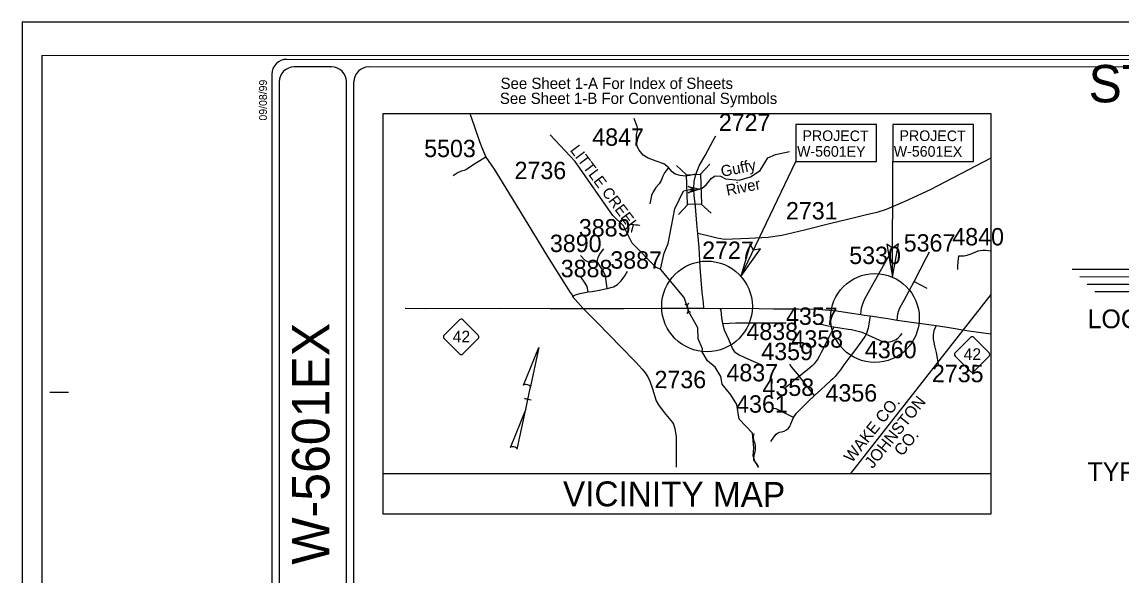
# Model space of a CAD drawing. Extents: x 2105791 to 2114488, y 667759 to 673441.
# Drawn here: x 2105791 to 2109589, y 671528 to 673441 of the extents above; entities that cross this region are included whole.
import ezdxf

# ---------------------------------------------------------------- set-up
doc = ezdxf.new("R2010")
doc.units = 0
for name, color, linetype in [('Default', 7, 'Continuous'), ('Exist Boundary Political CountyLine', 7, 'Continuous'), ('Exist Road Primary NC Attributed', 7, 'Continuous'), ('Exist Road Secondary Type 51 Attributed', 7, 'Continuous'), ('Old_Level_1', 7, 'Continuous'), ('Old_Level_8', 7, 'Continuous'), ('Prop North Arrow for Plan Sheets CELL', 7, 'Continuous'), ('Prop PHM Highway Shield CELL', 7, 'Continuous'), ('Sheet Cutting Line CELL', 7, 'Continuous'), ('Sheet Plot Border Inside CELL', 7, 'Continuous'), ('Sheet Plot Border Outside CELL', 7, 'Continuous'), ('Sheet Title CELL', 7, 'Continuous')]:
    doc.layers.add(name, color=color, linetype=linetype)

msp = doc.modelspace()

# ---------------------------------------------------------------- linework, layer by layer
at = {"layer": 'Default'}
for p, q in [((2108053.4, 672945.8), (2108087.6, 672913.7)), ((2108167.8, 672949.5), (2108135.6, 672915.2)), ((2108091.7, 672810.9), (2108059.6, 672776.7)), ((2108138.7, 672812.4), (2108172.9, 672780.3)), ((2108081.8, 672466.4), (2108089.4, 672462.3)), ((2108094, 672469.6), (2108089.4, 672462.3)), ((2108089.4, 672462.3), (2108094.6, 672442.3)), ((2108090, 672435), (2108094.6, 672442.3)), ((2108102.1, 672438.2), (2108094.6, 672442.3))]:
    msp.add_line(p, q, dxfattribs=at)
for points in [[(2107997.2, 672587.5), (2107982.4, 672593.3), (2107900.2, 672677.4), (2107869.3, 672737.3), (2107833.3, 672772.7), (2107702.9, 672959.2), (2107616.4, 673051.2)], [(2108077.1, 672857.7), (2108098.9, 672862.3), (2108103.9, 672862.9), (2108112.7, 672862.5), (2108117.5, 672861.9), (2108141.4, 672867.2), (2108155.4, 672878.9), (2108173.4, 672902.2), (2108186.5, 672910), (2108205.3, 672909), (2108222.1, 672899.3), (2108269, 672895.2), (2108308.9, 672905.9), (2108342.4, 672927.8), (2108369, 672971.5), (2108394.6, 672983.2), (2108443.8, 672993.2)], [(2108112.7, 672862.5), (2108112.7, 672867.6), (2108114.5, 672890.3), (2108119.7, 672914.3)], [(2107997.2, 672587.5), (2108010.2, 672642.9), (2108024.4, 672675.7), (2108046.7, 672796), (2108077.1, 672857.7)], [(2108335.9, 671904.3), (2108323.1, 671925.2), (2108318.3, 671943.5), (2108319.6, 671970.7), (2108315.7, 672020.9), (2108269.3, 672069.6), (2108261.3, 672120.8), (2108240.6, 672153.8), (2108210.7, 672190.6), (2108206, 672216.4), (2108186.8, 672248.9), (2108159.5, 672270.8), (2108141.4, 672302), (2108142.2, 672312.1), (2108127.7, 672347.1), (2108127, 672385.1), (2108100, 672432.7), (2108094.8, 672437.7), (2108093.5, 672440.8), (2108093.3, 672447.1), (2108092, 672452.3), (2108090.3, 672458.2), (2108079.6, 672490.2), (2107997.2, 672587.5)], [(2108320, 672020), (2108318.8, 672015.8), (2108317.9, 672010), (2108317.5, 672006.6), (2108318.7, 671998.7), (2108320.2, 671994.6), (2108322.1, 671989), (2108324, 671984.4), (2108325.3, 671979.3), (2108325, 671971.3), (2108324.2, 671964.2), (2108323.2, 671957.5), (2108322, 671951.9), (2108320.1, 671944.5), (2108318.6, 671934.4), (2108318.5, 671933.8), (2108319.5, 671928.3), (2108321.9, 671925.1), (2108325.7, 671920.1), (2108329.6, 671915.4), (2108332.4, 671910.4), (2108335.8, 671904.3)]]:
    msp.add_lwpolyline(points, dxfattribs=at)
for points in [[(2108135.6, 672915.2), (2108138.9, 672812.4), (2108090.9, 672810.9), (2108087.6, 672913.7)], [(2108093, 672872.5), (2108133.5, 672863.3), (2108093.8, 672851), (2108112.7, 672862.5)]]:
    msp.add_lwpolyline(points, close=True, dxfattribs=at)
at = {"layer": 'Exist Boundary Political CountyLine'}
msp.add_line((2109139.4, 672500.5), (2108653.7, 671882.4), dxfattribs=at)
at = {"layer": 'Exist Road Primary NC Attributed'}
for points in [[(2107115.1, 672452.3), (2107181.9, 672451.6), (2107444.8, 672452.4), (2107615.9, 672451.2), (2107730.3, 672451.2)], [(2107730.3, 672451.2), (2107776.1, 672451.5), (2107871.3, 672451.6), (2108005.8, 672452.4), (2108092, 672452.3), (2108146.9, 672452.6)], [(2108146.9, 672452.6), (2108202.2, 672452.1)], [(2108202.2, 672452.1), (2108288.9, 672452.5), (2108388.4, 672451), (2108474.1, 672450.2), (2108543, 672449.7), (2108607, 672444.1)], [(2108607, 672444.1), (2108659.3, 672436), (2108689.5, 672431)], [(2108689.5, 672431), (2108701.5, 672429), (2108721.9, 672425.9)], [(2108721.9, 672425.9), (2108783.3, 672416.7), (2108815.5, 672411.6)], [(2108815.5, 672411.6), (2108857, 672405.1), (2108949.7, 672392.7)], [(2108949.7, 672392.7), (2108988.3, 672386.8), (2109062.8, 672374.4), (2109139.4, 672364.8)]]:
    msp.add_lwpolyline(points, dxfattribs=at)
at = {"layer": 'Exist Road Secondary Type 51 Attributed'}
for p, q in [((2107393.9, 672974.3), (2107361.3, 672954.5)), ((2108873.8, 672544.9), (2108918, 672521.6))]:
    msp.add_line(p, q, dxfattribs=at)
for points in [[(2107339, 673124.8), (2107353.9, 673082.4), (2107372.5, 673028.4), (2107380.4, 673007.3), (2107393.9, 672974.3)], [(2108024.8, 672938.8), (2108009.1, 672950.7), (2107983.1, 672960.4), (2107954.7, 672970.8), (2107937.3, 672981.1), (2107923.5, 672998.6), (2107917.2, 673010.9), (2107914.3, 673031.6), (2107915.2, 673052.9), (2107919.1, 673071), (2107916.6, 673079.9), (2107906.8, 673107.7)], [(2108119.7, 672914.3), (2108131.7, 672943.7), (2108151.5, 672979.9), (2108179.9, 673031.8), (2108188.7, 673047.6)], [(2107361.3, 672954.5), (2107328.8, 672933.1), (2107324.4, 672930.6), (2107319, 672928.3), (2107314.2, 672926.7), (2107309.3, 672925.3), (2107303.9, 672923.6), (2107298.9, 672921.3), (2107294.4, 672918.6), (2107280.6, 672910)], [(2107393.9, 672974.3), (2107422.7, 672932.3), (2107472.5, 672851.7), (2107555.7, 672715.9), (2107607.5, 672631.6), (2107663.3, 672541.9), (2107685, 672506.8), (2107695.3, 672492.6)], [(2109139.4, 672970.9), (2108929.4, 672861.6), (2108841.6, 672820.6), (2108778, 672793.3), (2108744.8, 672783.1), (2108709.6, 672775.1), (2108667.7, 672764.4), (2108586.2, 672744.6), (2108494.9, 672722.2), (2108417.1, 672703.8), (2108369.8, 672696.9), (2108303.4, 672693.4), (2108219.2, 672689.9)], [(2108024.8, 672938.8), (2108011.5, 672920.3), (2108005.3, 672908.5), (2108000, 672893.6), (2107992.7, 672881.7), (2107981.7, 672869.4), (2107972.7, 672854.6), (2107966.4, 672842.1), (2107960.2, 672812.8)], [(2108119.7, 672914.3), (2108114.2, 672914.2), (2108098.9, 672910.8), (2108083.5, 672908.9), (2108065.9, 672910.3), (2108048.5, 672915.7), (2108038, 672923.9), (2108024.8, 672938.8)], [(2108126.4, 672710.5), (2108123.6, 672745.7), (2108119, 672804.2), (2108113.8, 672841.7), (2108112.7, 672862.5)], [(2108219.2, 672689.9), (2108193.7, 672694.6), (2108160.8, 672702.7), (2108126.4, 672710.5)], [(2108146.9, 672452.6), (2108146.1, 672471.2), (2108141.7, 672508.3), (2108135.1, 672592.7), (2108131.8, 672662.7), (2108126.4, 672710.5)], [(2107778.2, 672614.4), (2107781.8, 672628), (2107787.2, 672637.8), (2107801.8, 672657.6)], [(2108689.5, 672431), (2108692.7, 672453.5), (2108696.8, 672467.7), (2108702.7, 672482.6), (2108715.2, 672505.8), (2108737.6, 672545.2), (2108793.4, 672645.2)], [(2108873.8, 672544.9), (2108916, 672625.9), (2108927.4, 672647.7)], [(2109139.4, 672649.8), (2109121.6, 672651.7), (2109119.1, 672651.9), (2109112.1, 672651.7), (2109102.2, 672650.6), (2109094.2, 672649.3), (2109086, 672646.4), (2109069.7, 672639.3), (2109056.2, 672634.5), (2109047.3, 672632.8), (2109037.1, 672632), (2109027, 672632.5)], [(2107778.2, 672614.4), (2107768.3, 672611.2), (2107757.3, 672610.7), (2107746.4, 672612.4), (2107735.9, 672618.9), (2107720.9, 672634.1)], [(2107813.8, 672520.2), (2107811.4, 672538.5), (2107807.6, 672564.5), (2107801.8, 672577), (2107792.8, 672592.2), (2107778.2, 672614.4)], [(2109027, 672632.5), (2109025.2, 672615.1), (2109024, 672595.5), (2109024.4, 672586.6)], [(2107813.8, 672520.2), (2107835.7, 672526.2), (2107848.5, 672535), (2107861.8, 672546.7), (2107874.6, 672564.2), (2107884, 672581)], [(2107747.3, 672508.7), (2107744, 672527.8), (2107737.8, 672538.7), (2107722.4, 672560.6)], [(2108815.5, 672411.6), (2108818.3, 672432.9), (2108821.5, 672444.8), (2108826.3, 672455.8), (2108839.8, 672480.6), (2108873.8, 672544.9)], [(2107693.7, 672493.2), (2107703.4, 672498.9), (2107718.6, 672503.7), (2107747.3, 672508.7)], [(2107693.7, 672493.2), (2107730.3, 672451.2)], [(2107747.3, 672508.7), (2107760.9, 672510.7), (2107779.7, 672513.4), (2107813.8, 672520.2)], [(2107730.3, 672451.2), (2107745.2, 672437), (2107775.4, 672407), (2107823.4, 672357.1), (2107858.3, 672321.9), (2107913.3, 672264.8), (2107934.2, 672242.5), (2107944.4, 672229.9), (2107953.3, 672216), (2107960.4, 672201.3), (2107969.7, 672174.3), (2107982.5, 672132.4), (2107990.4, 672119.2), (2108010.1, 672092.9), (2108033.6, 672064.8), (2108039.1, 672057.9), (2108042.3, 672052.9), (2108047.6, 672037.6), (2108051.4, 672009), (2108052.1, 671904.3)], [(2108202.2, 672452.1), (2108206.1, 672446), (2108208, 672419), (2108211.6, 672400.4)], [(2108721.9, 672425.9), (2108717.9, 672398), (2108716.6, 672390.2), (2108715.1, 672383.4), (2108713.3, 672376.5), (2108710.6, 672369), (2108707.8, 672362.8)], [(2108211.6, 672400.4), (2108258.2, 672402.2), (2108346.2, 672402.7), (2108431.4, 672402)], [(2108211.6, 672400.4), (2108217.9, 672377.9), (2108232.3, 672345.4), (2108246.4, 672312.5), (2108253.5, 672301.6), (2108269.4, 672291.2), (2108291.9, 672280.9), (2108344.1, 672258.4)], [(2108596.9, 672386.9), (2108579.7, 672352.3), (2108563.8, 672322), (2108552.7, 672300.3), (2108545.6, 672285.7), (2108539.8, 672275.7), (2108536.1, 672270.1), (2108532.4, 672265.2), (2108528.6, 672260.3), (2108521, 672252.8), (2108505.5, 672239.7), (2108477.5, 672217.7)], [(2108596, 672387.1), (2108571.4, 672392.3), (2108552.9, 672396), (2108548.8, 672396.8)], [(2108707.8, 672362.8), (2108694.6, 672368.7), (2108686.1, 672371.5), (2108676.5, 672373.9), (2108657.6, 672377.6), (2108645.8, 672379.7), (2108596, 672387.1)], [(2108949.7, 672392.7), (2108942.6, 672374.9), (2108940.1, 672361.2), (2108939.5, 672346.4), (2108945, 672322.6), (2108949.8, 672299.4), (2108958, 672252.9)], [(2108707.8, 672362.8), (2108703.5, 672354.6), (2108693.6, 672339.6), (2108671.2, 672310.2), (2108645.1, 672275.1), (2108631.6, 672257.4), (2108619.1, 672240.2), (2108607.6, 672226.1), (2108601.1, 672217), (2108592.8, 672208.7), (2108585.4, 672202.2), (2108568.6, 672186.5), (2108551.4, 672171.1), (2108530.3, 672151.8)], [(2108707.8, 672362.8), (2108726.6, 672355.3), (2108742.2, 672347.8), (2108754.3, 672341.8), (2108764.3, 672337.6), (2108770, 672336.2), (2108776.1, 672335.3), (2108782.3, 672335.1), (2108789.2, 672336.1), (2108797.9, 672338.5), (2108806.7, 672341.9), (2108812.2, 672344.8), (2108818.9, 672350), (2108825.9, 672357.7), (2108832.3, 672365.7)], [(2108477.5, 672217.7), (2108450.4, 672250.2), (2108444.2, 672259.2)], [(2108477.5, 672217.7), (2108460, 672203.8), (2108441.8, 672188.4), (2108428.7, 672178.3)], [(2108530.3, 672151.8), (2108506.9, 672179.9), (2108490.8, 672200.9), (2108481.3, 672212.4), (2108477.5, 672217.7)], [(2108456.9, 672074.9), (2108467.3, 672090.4), (2108506.4, 672129.6), (2108530.3, 672151.8)], [(2108456.9, 672074.9), (2108396.9, 672105.2), (2108388.8, 672106.9)], [(2108378.6, 671992.3), (2108379.1, 671993), (2108389.6, 672007.1), (2108397.7, 672018.3), (2108401.9, 672021.4), (2108409.1, 672024.3), (2108415.7, 672025.8), (2108425.5, 672028.5), (2108433.5, 672032.8), (2108440.1, 672038.6), (2108444.6, 672044.7), (2108448.1, 672053.5), (2108456.9, 672074.9)]]:
    msp.add_lwpolyline(points, dxfattribs=at)
at = {"layer": 'Old_Level_1'}
for p, q in [((2108275.8, 672562.5), (2108465.4, 672958.8)), ((2108799.6, 672559.6), (2108800.6, 672958.8)), ((2107039.3, 671882.4), (2109139.4, 671882.4)), ((2109139.4, 671909.1), (2109139.4, 671901.3))]:
    msp.add_line(p, q, dxfattribs=at)
msp.add_lwpolyline([(2109139.4, 671901.3), (2109139.4, 671742.1), (2107039.3, 671742.1), (2107039.3, 673124.8), (2109139.4, 673124.8), (2109139.4, 671909.1)], dxfattribs=at)
for points in [[(2108465.4, 672958.8), (2108744.2, 672958.8), (2108744.2, 673086.6), (2108465.4, 673086.7)], [(2108800.6, 672958.8), (2109079.4, 672958.8), (2109079.4, 673086.6), (2108800.6, 673086.7)], [(2108307.4, 672674.1), (2108275.8, 672562.5), (2108343.7, 672657.4), (2108319.1, 672653)], [(2108780.2, 672674), (2108799.6, 672559.6), (2108820.2, 672674.6), (2108799.8, 672660)]]:
    msp.add_lwpolyline(points, close=True, dxfattribs=at)
for centre, radius in [((2108158.4, 672458.8), 156.6), ((2108738.4, 672418.8), 153.5)]:
    msp.add_circle(centre, radius, dxfattribs=at)
at = {"layer": 'Prop North Arrow for Plan Sheets CELL'}
for p, q in [((2107524.3, 672186.7), (2107577.5, 672317.6)), ((2107577.6, 672317.5), (2107547.6, 672177.3)), ((2107577.6, 672317.5), (2107577.5, 672317.6)), ((2107577.6, 672317.5), (2107577.5, 672317.6)), ((2107532.1, 672104.5), (2107548.5, 672181.4)), ((2107547.6, 672177.3), (2107548.5, 672181.3)), ((2107527.6, 672141.1), (2107527.5, 672141.1)), ((2107538, 672138.8), (2107527.6, 672141.1)), ((2107527.8, 672141), (2107551.2, 672136)), ((2107532.1, 672104.5), (2107478, 671971.1)), ((2107502.7, 671966.5), (2107532.1, 672104.5))]:
    msp.add_line(p, q, dxfattribs=at)
for centre, start_param, end_param in [((2107536.2, 672182.7), 0.216388, 2.908219), ((2107490.3, 671968), 0.201328, 3.141593)]:
    msp.add_ellipse(centre, major_axis=(12.4, -2.7), ratio=0.461098, start_param=start_param, end_param=end_param, dxfattribs=at)
at = {"layer": 'Prop PHM Highway Shield CELL'}
for p, q in [((2107249.7, 672359.5), (2107303, 672412.6)), ((2107314.4, 672412.6), (2107367.5, 672359.3)), ((2107247.4, 672354.3), (2107247.4, 672354.3)), ((2107302.8, 672294.9), (2107249.7, 672348.1)), ((2107367.5, 672347.9), (2107314.2, 672294.9)), ((2109015.4, 672298.8), (2109068.7, 672351.8)), ((2109080.1, 672351.8), (2109133.2, 672298.6)), ((2109013.1, 672293.5), (2109013.1, 672293.6)), ((2109068.5, 672234.1), (2109015.4, 672287.4)), ((2109133.2, 672287.2), (2109079.9, 672234.1))]:
    msp.add_line(p, q, dxfattribs=at)
for centre, start, end in [((2107308.7, 672406.9), 93.1291, 134.9188), ((2107308.7, 672406.9), 44.9188, 92.9952), ((2107255.4, 672353.8), 134.9188, 176.3258), ((2107255.4, 672353.8), 176.4784, 224.9188), ((2107361.8, 672353.6), 1.8482, 44.9188), ((2107361.8, 672353.6), 314.9188, 1.6571), ((2109074.4, 672346.1), 93.1291, 134.9188), ((2109074.4, 672346.1), 44.9188, 92.9952), ((2109021.1, 672293.1), 134.9188, 176.3258), ((2109127.5, 672292.9), 1.8482, 44.9188), ((2107308.5, 672300.6), 224.9188, 264.9661), ((2107308.5, 672300.6), 265.1003, 314.9188), ((2109021.1, 672293.1), 176.4784, 224.9188), ((2109127.5, 672292.9), 314.9188, 1.6571), ((2109074.2, 672239.8), 224.9188, 264.9661), ((2109074.2, 672239.8), 265.1003, 314.9188)]:
    msp.add_arc(centre, 8.06, start, end, dxfattribs=at)
at = {"layer": 'Sheet Cutting Line CELL'}
for q in [(2105791, 667760.7), (2114487.7, 673439.3)]:
    msp.add_line((2105792, 673440.8), q, dxfattribs=at)
at = {"layer": 'Sheet Plot Border Inside CELL'}
msp.add_lwpolyline([(2105858.2, 667876.6), (2114463.6, 667875.1), (2114464.5, 673323.4), (2105859.1, 673324.8)], close=True, dxfattribs=at)
at = {"layer": 'Sheet Plot Border Outside CELL'}
msp.add_lwpolyline([(2114487.7, 673439.3), (2105792, 673440.8), (2105791, 667760.7), (2114486.8, 667759.2)], close=True, dxfattribs=at)
at = {"layer": 'Sheet Title CELL'}
for p, q in [((2106911.6, 667967.1), (2106912.5, 673234.1)), ((2106937.6, 668922.4), (2106938.3, 673234.1)), ((2109420.7, 672587.4), (2111620.4, 672587)), ((2109446.5, 672561.6), (2111594.6, 672561.2)), ((2109472.3, 672535.7), (2111568.8, 672535.4)), ((2109498.1, 672510), (2111542.9, 672509.6)), ((2105887.3, 672162.7), (2105951.8, 672162.7)), ((2105887.3, 672162.7), (2105951.8, 672162.7))]:
    msp.add_line(p, q, dxfattribs=at)
for points in [[(2114348.4, 673310.2), (2106705.9, 673311.6)], [(2106860.8, 673285.7), (2106731.8, 673285.8)], [(2114322.5, 673284.4), (2106990, 673285.7)], [(2106654.3, 673260), (2106653.4, 667941.3)], [(2106654.3, 673260), (2106653.4, 667941.3)], [(2106680.2, 673234.1), (2106679.2, 667967.1)]]:
    msp.add_lwpolyline(points, dxfattribs=at)
for centre, start, end in [((2106705.9, 673260.2), 89.9903, 179.9903), ((2106731.8, 673234.4), 89.9903, 179.9903), ((2106860.9, 673234.3), 359.9903, 89.9903), ((2106990, 673234.3), 89.9903, 179.9903)]:
    msp.add_arc(centre, 51.6, start, end, dxfattribs=at)

# ---------------------------------------------------------------- texts
at = {"layer": 'Default'}
for s, height, rotation, p in [('LITTLE CREEK', 38.285, 306.9522, (2107683.4, 672998.2)), ('Guffy', 38.29, 11.4692, (2108210.1, 672905.7)), ('River', 38.29, 11.4692, (2108228.3, 672840.7))]:
    msp.add_text(s, height=height, rotation=rotation, dxfattribs=at).set_placement(p)
at = {"layer": 'Exist Boundary Political CountyLine'}
for s, p in [('JOHNSTON ', (2108730.6, 671896.6)), ('WAKE CO.', (2108659.1, 671916.6)), ('CO.', (2108832.6, 671939))]:
    msp.add_text(s, height=40.5, rotation=51.2991, dxfattribs=at).set_placement(p)
at = {"layer": 'Old_Level_1'}
for s, height, rotation, p in [('PROJECT', 36.61, 359.7111, (2108488.3, 673030.4)), ('PROJECT', 36.61, 359.7111, (2108823.6, 673030.4)), ('W-5601EY', 36.61, 359.7111, (2108469.4, 672976.3)), ('W-5601EX', 36.61, 359.7111, (2108803.6, 672976.3)), ('VICINITY MAP', 86.142, 359.7803, (2107660.2, 671769.2))]:
    msp.add_text(s, height=height, rotation=rotation, dxfattribs=at).set_placement(p)
at = {"layer": 'Old_Level_8'}
for s, p in [('2727', (2108199.1, 673064.5)), ('4847', (2107761.8, 673013.6)), ('5503', (2107180.8, 672974.3)), ('2736', (2107493.2, 672898.4)), ('2731', (2108431.2, 672759.2)), ('3889', (2107715.4, 672700.5)), ('4840', (2109006, 672669.6)), ('3890', (2107615.4, 672646.6)), ('2727', (2108141.5, 672623.1)), ('5367', (2108838.1, 672648.3)), ('3887', (2107824.2, 672589.3)), ('5330', (2108649.9, 672605.3)), ('3888', (2107652.9, 672559.8)), ('4357', (2108431.3, 672395.3)), ('4838', (2108294.6, 672342.8)), ('4358', (2108450.2, 672316.7)), ('4359', (2108345.9, 672273.5)), ('4360', (2108704, 672280)), ('4837', (2108225.5, 672200.4)), ('2735', (2108935.5, 672197.4)), ('2736', (2107976.8, 672176.7)), ('4358', (2108350.1, 672150)), ('4356', (2108567.9, 672130.5)), ('4361', (2108258.9, 672092.1))]:
    msp.add_text(s, height=60, rotation=359.932, dxfattribs=at).set_placement(p)
at = {"layer": 'Prop PHM Highway Shield CELL'}
for p in [(2107279.5, 672334.6), (2109045.2, 672273.8)]:
    msp.add_text('42', height=40.5, rotation=359.9188, dxfattribs=at).set_placement(p)
at = {"layer": 'Sheet Title CELL'}
for s, height, rotation, p in [('STATE OF NORTH CAROLINA', 129.093, 359.9903, (2109476.8, 673163.4)), ('See Sheet 1-A For Index of Sheets', 38.728, 359.9903, (2107444.9, 673209.7)), ('09/08/99', 27.11, 89.9903, (2106637.5, 673100.5)), ('See Sheet 1-B For Conventional Symbols', 38.728, 359.9903, (2107442.5, 673157.9)), ('LOCATION: ', 64.55, 359.9903, (2109473.3, 672383.7)), ('W-5601EX', 129.09, 89.9903, (2106853.4, 671567.5)), ('TYPE OF WORK:', 64.547, 359.9903, (2109473.2, 671856.3))]:
    msp.add_text(s, height=height, rotation=rotation, dxfattribs=at).set_placement(p)

doc.saveas('drawing.dxf')
